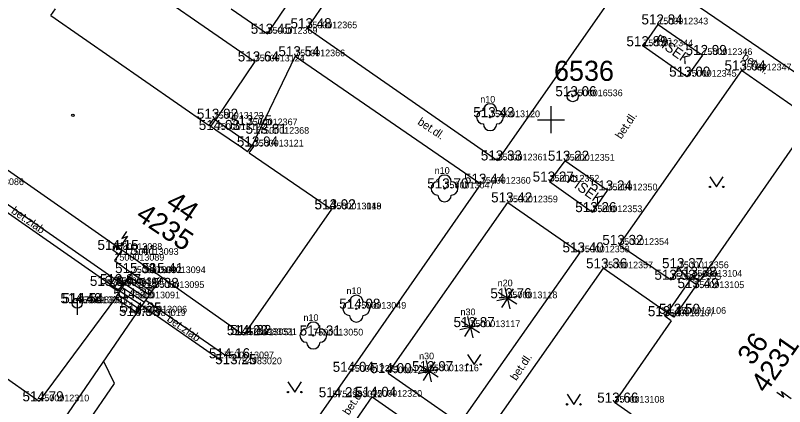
# Model space of a CAD drawing. Extents: x -669251 to -668549, y -1128351 to -1127698.
# Drawn here: x -668989.9 to -668932.6, y -1127921.4 to -1127892.2 of the extents above; entities that cross this region are included whole.
import ezdxf

# ---------------------------------------------------------------- set-up
doc = ezdxf.new("R2010")
doc.units = 0
for name, color, linetype in [('Vrstva 1', 7, 'Continuous'), ('Vrstva 10', 7, 'Continuous'), ('Vrstva 11', 7, 'Continuous'), ('Vrstva 2', 7, 'Continuous'), ('Vrstva 21', 7, 'Continuous'), ('Vrstva 22', 7, 'Continuous'), ('Vrstva 24', 7, 'Continuous'), ('Vrstva 27', 7, 'Continuous'), ('Vrstva 3', 7, 'Continuous'), ('Vrstva 36', 7, 'Continuous'), ('Vrstva 40', 7, 'Continuous'), ('Vrstva 42', 7, 'Continuous'), ('Vrstva 43', 7, 'Continuous'), ('Vrstva 44', 7, 'Continuous'), ('Vrstva 47', 7, 'Continuous'), ('Vrstva 5', 7, 'Continuous'), ('Vrstva 58', 7, 'Continuous'), ('Vrstva 6', 7, 'Continuous'), ('Vrstva 61', 7, 'Continuous'), ('Vrstva 63', 7, 'Continuous')]:
    doc.layers.add(name, color=color, linetype=linetype)

msp = doc.modelspace()

# ---------------------------------------------------------------- linework, layer by layer
at = {"layer": 'Vrstva 1'}
for p, q in [((-668968.152, -1127893.186), (-668968.152, -1127893.186)), ((-668942.004, -1127892.9), (-668942.004, -1127892.9)), ((-668971.113, -1127893.598), (-668971.113, -1127893.598)), ((-668943.121, -1127894.526), (-668943.121, -1127894.526)), ((-668969.052, -1127895.274), (-668969.052, -1127895.274)), ((-668938.713, -1127895.179), (-668938.713, -1127895.179)), ((-668972.065, -1127895.659), (-668972.065, -1127895.659)), ((-668935.793, -1127896.328), (-668935.793, -1127896.328)), ((-668939.885, -1127896.794), (-668939.885, -1127896.794)), ((-668948.374, -1127898.252), (-668948.374, -1127898.252)), ((-668975.121, -1127899.931), (-668975.121, -1127899.931)), ((-668954.534, -1127899.815), (-668954.534, -1127899.815)), ((-668972.591, -1127900.414), (-668972.591, -1127900.414)), ((-668974.965, -1127900.77), (-668974.965, -1127900.77)), ((-668971.732, -1127901.049), (-668971.732, -1127901.049)), ((-668972.14, -1127902), (-668972.14, -1127902)), ((-668953.974, -1127903.041), (-668953.974, -1127903.041)), ((-668948.971, -1127903.063), (-668948.971, -1127903.063)), ((-668950.109, -1127904.616), (-668950.109, -1127904.616)), ((-668957.927, -1127905.125), (-668957.927, -1127905.125)), ((-668955.225, -1127904.774), (-668955.225, -1127904.774)), ((-668945.78, -1127905.276), (-668945.78, -1127905.276)), ((-668953.204, -1127906.167), (-668953.204, -1127906.167)), ((-668966.349, -1127906.681), (-668966.349, -1127906.681)), ((-668966.345, -1127906.688), (-668966.345, -1127906.688)), ((-668946.914, -1127906.894), (-668946.914, -1127906.894)), ((-668982.675, -1127909.708), (-668982.675, -1127909.708)), ((-668944.918, -1127909.338), (-668944.918, -1127909.338)), ((-668981.455, -1127910.08), (-668981.455, -1127910.08)), ((-668947.848, -1127909.893), (-668947.848, -1127909.893)), ((-668982.522, -1127910.509), (-668982.522, -1127910.509)), ((-668981.221, -1127911.439), (-668981.221, -1127911.439)), ((-668979.441, -1127911.438), (-668979.441, -1127911.438)), ((-668946.11, -1127911.079), (-668946.11, -1127911.079)), ((-668940.472, -1127911.072), (-668940.472, -1127911.072)), ((-668941.039, -1127911.936), (-668941.039, -1127911.936)), ((-668939.463, -1127911.706), (-668939.463, -1127911.706)), ((-668983.093, -1127912.392), (-668983.093, -1127912.392)), ((-668982.348, -1127912.262), (-668982.348, -1127912.262)), ((-668979.542, -1127912.543), (-668979.542, -1127912.543)), ((-668939.317, -1127912.557), (-668939.317, -1127912.557)), ((-668985.29, -1127913.682), (-668985.29, -1127913.682)), ((-668985.152, -1127913.68), (-668985.152, -1127913.68)), ((-668981.354, -1127913.322), (-668981.354, -1127913.322)), ((-668953.239, -1127913.311), (-668953.239, -1127913.311)), ((-668980.823, -1127914.376), (-668980.823, -1127914.376)), ((-668964.498, -1127914.091), (-668964.498, -1127914.091)), ((-668980.928, -1127914.633), (-668980.928, -1127914.633)), ((-668941.525, -1127914.651), (-668941.525, -1127914.651)), ((-668940.671, -1127914.472), (-668940.671, -1127914.472)), ((-668956.005, -1127915.465), (-668956.005, -1127915.465)), ((-668972.898, -1127916.064), (-668972.898, -1127916.064)), ((-668972.649, -1127916.053), (-668972.649, -1127916.053)), ((-668967.704, -1127916.089), (-668967.704, -1127916.089)), ((-668974.35, -1127917.788), (-668974.35, -1127917.788)), ((-668973.762, -1127918.23), (-668973.762, -1127918.23)), ((-668964.983, -1127918.797), (-668964.983, -1127918.797)), ((-668962.136, -1127918.896), (-668962.136, -1127918.896)), ((-668959.092, -1127918.751), (-668959.092, -1127918.751)), ((-668966.283, -1127920.691), (-668966.283, -1127920.691)), ((-668963.314, -1127920.66), (-668963.314, -1127920.66)), ((-668988.115, -1127920.994), (-668988.115, -1127920.994)), ((-668945.266, -1127921.095), (-668945.266, -1127921.095))]:
    msp.add_line(p, q, dxfattribs=at)
at = {"layer": 'Vrstva 10'}
for p, q in [((-668932.638, -1127872.499), (-668953.974, -1127903.041)), ((-668958.428, -1127878.805), (-668968.152, -1127893.186)), ((-668984.978, -1127886.729), (-668972.065, -1127895.659)), ((-668971.113, -1127893.598), (-668968.407, -1127889.606)), ((-668941.646, -1127889.728), (-668930.773, -1127897.183)), ((-668973.834, -1127891.738), (-668971.113, -1127893.598)), ((-668968.152, -1127893.186), (-668953.974, -1127903.041)), ((-668943.121, -1127894.526), (-668942.004, -1127892.9)), ((-668942.004, -1127892.9), (-668938.713, -1127895.179)), ((-668939.885, -1127896.794), (-668943.121, -1127894.526)), ((-668969.052, -1127895.274), (-668972.264, -1127901.915)), ((-668969.052, -1127895.274), (-668955.225, -1127904.774)), ((-668938.713, -1127895.179), (-668939.885, -1127896.794)), ((-668972.065, -1127895.659), (-668974.998, -1127900.017)), ((-668935.793, -1127896.328), (-668944.918, -1127909.338)), ((-668931.053, -1127899.649), (-668935.793, -1127896.328)), ((-668948.971, -1127903.063), (-668950.109, -1127904.616)), ((-668945.78, -1127905.276), (-668948.971, -1127903.063)), ((-668992.837, -1127904.672), (-668981.814, -1127912.341)), ((-668950.109, -1127904.616), (-668946.914, -1127906.894)), ((-668993.125, -1127905.08), (-668982.1, -1127912.776)), ((-668955.225, -1127904.774), (-668964.983, -1127918.797)), ((-668946.914, -1127906.894), (-668945.78, -1127905.276)), ((-668962.136, -1127918.896), (-668953.204, -1127906.167)), ((-668953.204, -1127906.167), (-668947.848, -1127909.893)), ((-668944.918, -1127909.338), (-668941.039, -1127911.936)), ((-668947.848, -1127909.893), (-668956.786, -1127922.617)), ((-668946.11, -1127911.079), (-668955.055, -1127923.813)), ((-668941.343, -1127914.388), (-668946.11, -1127911.079)), ((-668941.039, -1127911.936), (-668940.472, -1127911.072)), ((-668940.472, -1127911.072), (-668939.646, -1127911.969)), ((-669000.837, -1127912.018), (-668988.115, -1127920.994)), ((-668982.449, -1127913.307), (-668988.115, -1127920.994)), ((-668980.174, -1127913.447), (-668974.208, -1127917.583)), ((-668986.272, -1127922.324), (-668980.823, -1127914.376)), ((-668980.459, -1127913.855), (-668974.492, -1127917.993)), ((-668962.136, -1127918.896), (-668956.786, -1127922.617)), ((-668971.938, -1127933.04), (-668963.314, -1127920.66)), ((-668963.314, -1127920.66), (-668958.065, -1127924.311))]:
    msp.add_line(p, q, dxfattribs=at)
msp.add_lwpolyline([(-668964.983, -1127918.797), (-668983.234, -1127944.915)], dxfattribs=at)
at = {"layer": 'Vrstva 11'}
for p, q in [((-668981.972, -1127909.72), (-668982.522, -1127910.509)), ((-668982.522, -1127910.509), (-668981.221, -1127911.439)), ((-668981.397, -1127911.706), (-668981.221, -1127911.439)), ((-668981.221, -1127911.439), (-668979.542, -1127912.543)), ((-668981.748, -1127912.241), (-668981.573, -1127911.974)), ((-668981.573, -1127911.974), (-668981.397, -1127911.706)), ((-668981.573, -1127911.974), (-668979.909, -1127913.068)), ((-668981.397, -1127911.706), (-668979.725, -1127912.805)), ((-668978.987, -1127911.759), (-668979.542, -1127912.543)), ((-668982.1, -1127912.776), (-668981.924, -1127912.509)), ((-668981.924, -1127912.509), (-668981.814, -1127912.341)), ((-668981.924, -1127912.509), (-668980.276, -1127913.593)), ((-668981.814, -1127912.341), (-668981.748, -1127912.241)), ((-668981.748, -1127912.241), (-668980.092, -1127913.33)), ((-668979.725, -1127912.805), (-668979.542, -1127912.543)), ((-668982.449, -1127913.307), (-668982.276, -1127913.043)), ((-668982.276, -1127913.043), (-668982.1, -1127912.776)), ((-668982.276, -1127913.043), (-668980.642, -1127914.117)), ((-668982.1, -1127912.776), (-668980.459, -1127913.855)), ((-668980.092, -1127913.33), (-668979.909, -1127913.068)), ((-668979.909, -1127913.068), (-668979.725, -1127912.805)), ((-668982.449, -1127913.307), (-668980.823, -1127914.376)), ((-668980.459, -1127913.855), (-668980.276, -1127913.593)), ((-668980.276, -1127913.593), (-668980.174, -1127913.447)), ((-668980.174, -1127913.447), (-668980.092, -1127913.33)), ((-668980.823, -1127914.376), (-668980.642, -1127914.117)), ((-668980.642, -1127914.117), (-668980.459, -1127913.855))]:
    msp.add_line(p, q, dxfattribs=at)
at = {"layer": 'Vrstva 21'}
for p, q in [((-668982.505, -1127919.664), (-668983.319, -1127918.017)), ((-668984.984, -1127923.265), (-668982.505, -1127919.664))]:
    msp.add_line(p, q, dxfattribs=at)
at = {"layer": 'Vrstva 22'}
for p, q in [((-668953.247, -1127913.271), (-668953.419, -1127912.517)), ((-668952.805, -1127912.621), (-668953.219, -1127913.277)), ((-668953.273, -1127913.291), (-668953.929, -1127912.877)), ((-668953.199, -1127913.303), (-668952.445, -1127913.131)), ((-668954.033, -1127913.491), (-668953.279, -1127913.319)), ((-668953.259, -1127913.345), (-668953.673, -1127914.001)), ((-668953.231, -1127913.351), (-668953.059, -1127914.105)), ((-668952.549, -1127913.745), (-668953.205, -1127913.331)), ((-668956.013, -1127915.425), (-668956.185, -1127914.671)), ((-668955.571, -1127914.775), (-668955.985, -1127915.431)), ((-668956.799, -1127915.645), (-668956.045, -1127915.473)), ((-668956.039, -1127915.445), (-668956.695, -1127915.031)), ((-668956.025, -1127915.499), (-668956.439, -1127916.155)), ((-668955.997, -1127915.505), (-668955.825, -1127916.259)), ((-668955.315, -1127915.899), (-668955.971, -1127915.485)), ((-668955.965, -1127915.457), (-668955.211, -1127915.285)), ((-668959.126, -1127918.731), (-668959.782, -1127918.317)), ((-668959.1, -1127918.711), (-668959.272, -1127917.957)), ((-668958.658, -1127918.061), (-668959.072, -1127918.717)), ((-668959.886, -1127918.931), (-668959.132, -1127918.759)), ((-668959.112, -1127918.785), (-668959.526, -1127919.441)), ((-668959.084, -1127918.791), (-668958.912, -1127919.545)), ((-668958.402, -1127919.185), (-668959.058, -1127918.771)), ((-668959.052, -1127918.743), (-668958.298, -1127918.571))]:
    msp.add_line(p, q, dxfattribs=at)
for centre, radius in [((-668954.534, -1127899.815), 0.05), ((-668957.927, -1127905.125), 0.05), ((-668953.239, -1127913.311), 0.04), ((-668964.498, -1127914.091), 0.05), ((-668956.005, -1127915.465), 0.04), ((-668967.704, -1127916.089), 0.05), ((-668959.092, -1127918.751), 0.04)]:
    msp.add_circle(centre, radius, dxfattribs=at)
for centre, start, end in [((-668954.534, -1127899.315), 0, 180), ((-668955.034, -1127899.815), 90, 270), ((-668954.034, -1127899.815), 270, 90), ((-668954.534, -1127900.315), 180, 0), ((-668958.427, -1127905.125), 90, 270), ((-668957.927, -1127904.625), 0, 180), ((-668957.427, -1127905.125), 270, 90), ((-668957.927, -1127905.625), 180, 0), ((-668964.498, -1127913.591), 0, 180), ((-668964.998, -1127914.091), 90, 270), ((-668963.998, -1127914.091), 270, 90), ((-668964.498, -1127914.591), 180, 0), ((-668967.704, -1127915.589), 0, 180), ((-668968.204, -1127916.089), 90, 270), ((-668967.204, -1127916.089), 270, 90), ((-668967.704, -1127916.589), 180, 0)]:
    msp.add_arc(centre, 0.5, start, end, dxfattribs=at)
at = {"layer": 'Vrstva 24'}
for p, q in [((-668981.557, -1127908.688), (-668982.047, -1127909.413)), ((-668981.624, -1127908.34), (-668981.974, -1127908.859)), ((-668981.974, -1127908.859), (-668981.557, -1127908.688)), ((-668982.001, -1127909.148), (-668982.047, -1127909.413)), ((-668982.45, -1127909.386), (-668982.675, -1127909.708)), ((-668982.196, -1127910.042), (-668982.675, -1127909.708)), ((-668982.047, -1127909.413), (-668981.819, -1127909.271)), ((-668933.162, -1127920.312), (-668932.657, -1127920.682)), ((-668932.657, -1127920.682), (-668932.812, -1127920.259)), ((-668932.812, -1127920.259), (-668932.106, -1127920.776))]:
    msp.add_line(p, q, dxfattribs=at)
at = {"layer": 'Vrstva 27'}
for p, q in [((-668982.554, -1127912.575), (-668982.142, -1127911.949)), ((-668985.29, -1127913.307), (-668985.29, -1127914.557))]:
    msp.add_line(p, q, dxfattribs=at)
msp.add_lwpolyline([(-668982.242, -1127912.781), (-668981.829, -1127912.154), (-668982.456, -1127911.742), (-668982.868, -1127912.369)], close=True, dxfattribs=at)
msp.add_circle((-668985.29, -1127913.682), 0.375, dxfattribs=at)
at = {"layer": 'Vrstva 36'}
for p, q in [((-668938.156, -1127904.268), (-668937.656, -1127905.018)), ((-668937.656, -1127905.018), (-668937.156, -1127904.268)), ((-668956.228, -1127917.496), (-668955.728, -1127918.246)), ((-668955.728, -1127918.246), (-668955.228, -1127917.496)), ((-668969.59, -1127919.555), (-668969.09, -1127920.305)), ((-668969.09, -1127920.305), (-668968.59, -1127919.555)), ((-668948.796, -1127920.47), (-668948.296, -1127921.22)), ((-668948.296, -1127921.22), (-668947.796, -1127920.47))]:
    msp.add_line(p, q, dxfattribs=at)
for centre in [(-668938.156, -1127905.018), (-668937.156, -1127905.018), (-668956.228, -1127918.245), (-668955.228, -1127918.245), (-668969.589, -1127920.304), (-668968.589, -1127920.304), (-668948.796, -1127921.22), (-668947.796, -1127921.22)]:
    msp.add_circle(centre, 0.05, dxfattribs=at)
at = {"layer": 'Vrstva 5'}
for p, q in [((-668987.253, -1127892.235), (-668986.912, -1127891.744)), ((-668987.253, -1127892.235), (-668975.463, -1127900.424)), ((-668975.463, -1127900.424), (-668975.121, -1127899.931)), ((-668975.34, -1127900.509), (-668974.998, -1127900.017)), ((-668975.121, -1127899.931), (-668974.998, -1127900.017)), ((-668974.998, -1127900.017), (-668972.264, -1127901.915)), ((-668974.965, -1127900.77), (-668975.34, -1127900.509)), ((-668930.734, -1127900.212), (-668938.966, -1127912.052)), ((-668981.972, -1127909.72), (-668993.739, -1127901.513)), ((-668972.594, -1127902.397), (-668972.973, -1127902.136)), ((-668972.594, -1127902.397), (-668972.264, -1127901.915)), ((-668972.47, -1127902.481), (-668972.14, -1127902)), ((-668972.264, -1127901.915), (-668972.14, -1127902)), ((-668972.47, -1127902.481), (-668966.349, -1127906.681)), ((-668966.349, -1127906.681), (-668972.898, -1127916.064)), ((-668981.455, -1127910.08), (-668981.972, -1127909.72)), ((-668978.987, -1127911.759), (-668979.441, -1127911.438)), ((-668972.898, -1127916.064), (-668978.987, -1127911.759)), ((-668939.646, -1127911.969), (-668941.343, -1127914.388)), ((-668939.646, -1127911.969), (-668939.463, -1127911.706)), ((-668939.148, -1127912.314), (-668939.646, -1127911.969)), ((-668938.966, -1127912.052), (-668939.463, -1127911.706)), ((-668939.148, -1127912.314), (-668939.317, -1127912.557)), ((-668941.525, -1127914.651), (-668941.343, -1127914.388)), ((-668940.85, -1127914.73), (-668941.343, -1127914.388)), ((-668941.032, -1127914.993), (-668945.266, -1127921.095)), ((-668941.032, -1127914.993), (-668941.525, -1127914.651)), ((-668940.671, -1127914.472), (-668940.85, -1127914.73)), ((-668944.034, -1127921.95), (-668945.266, -1127921.095))]:
    msp.add_line(p, q, dxfattribs=at)
at = {"layer": 'Vrstva 58'}
msp.add_circle((-668985.618, -1127899.681), 0.0875, dxfattribs=at)
at = {"layer": 'Vrstva 6'}
for p, q in [((-668972.973, -1127902.136), (-668974.965, -1127900.77)), ((-668981.455, -1127910.08), (-668979.441, -1127911.438)), ((-668939.317, -1127912.557), (-668940.671, -1127914.472))]:
    msp.add_line(p, q, dxfattribs=at)
at = {"layer": 'Vrstva 61'}
for p, q in [((-668950, -1127899), (-668950, -1127901)), ((-668951, -1127900), (-668949, -1127900))]:
    msp.add_line(p, q, dxfattribs=at)
at = {"layer": 'Vrstva 63'}
for radius in [0.412, 0.412, 0.05, 0.05]:
    msp.add_circle((-668948.374, -1127898.252), radius, dxfattribs=at)

# ---------------------------------------------------------------- texts
at = {"layer": 'Vrstva 2'}
for s, p in [('7500012343', (-668942.004, -1127892.9)), ('7500012369', (-668971.113, -1127893.598)), ('7500012365', (-668968.152, -1127893.186)), ('7500012344', (-668943.121, -1127894.526)), ('7500012366', (-668969.052, -1127895.274)), ('7500012346', (-668938.713, -1127895.179)), ('7500013124', (-668972.065, -1127895.659)), ('7500012347', (-668935.793, -1127896.328)), ('7500012345', (-668939.885, -1127896.794)), ('7500016536', (-668948.374, -1127898.252)), ('7500013123', (-668975.121, -1127899.931)), ('7500013120', (-668954.534, -1127899.815)), ('7500012367', (-668972.591, -1127900.414)), ('7500013122', (-668974.965, -1127900.77)), ('7500012368', (-668971.732, -1127901.049)), ('7500013121', (-668972.14, -1127902)), ('7500012361', (-668953.974, -1127903.041)), ('7500012351', (-668948.971, -1127903.063)), ('7500012352', (-668950.109, -1127904.616)), ('7500013086', (-668992.981, -1127904.876)), ('7500013047', (-668957.927, -1127905.125)), ('7500012360', (-668955.225, -1127904.774)), ('7500012350', (-668945.78, -1127905.276)), ('7500012359', (-668953.204, -1127906.167)), ('7500013048', (-668966.349, -1127906.681)), ('7500013119', (-668966.345, -1127906.688)), ('7500012353', (-668946.914, -1127906.894)), ('7500013088', (-668982.675, -1127909.708)), ('7500012354', (-668944.918, -1127909.338)), ('7500013093', (-668981.455, -1127910.08)), ('7500012358', (-668947.848, -1127909.893)), ('7500013089', (-668982.522, -1127910.509)), ('7500013092', (-668981.221, -1127911.439)), ('7500013094', (-668979.441, -1127911.438)), ('7500012357', (-668946.11, -1127911.079)), ('7500012356', (-668940.472, -1127911.072)), ('7500012355', (-668941.039, -1127911.936)), ('7500013104', (-668939.463, -1127911.706)), ('5754983018', (-668983.093, -1127912.392)), ('7500013090', (-668982.348, -1127912.262)), ('7500013095', (-668979.542, -1127912.543)), ('7500013105', (-668939.317, -1127912.557)), ('7500013087', (-668985.29, -1127913.682)), ('5754983017', (-668985.152, -1127913.68)), ('7500013091', (-668981.354, -1127913.322)), ('7500013118', (-668953.239, -1127913.311)), ('7500013049', (-668964.498, -1127914.091)), ('5754983019', (-668980.928, -1127914.633)), ('7500013096', (-668980.823, -1127914.376)), ('7500013107', (-668941.525, -1127914.651)), ('7500013106', (-668940.671, -1127914.472)), ('7500013117', (-668956.005, -1127915.465)), ('7500013051', (-668972.898, -1127916.064)), ('5754983021', (-668972.649, -1127916.053)), ('7500013050', (-668967.704, -1127916.089)), ('7500013097', (-668974.35, -1127917.788)), ('5754983020', (-668973.762, -1127918.23)), ('7500012321', (-668964.983, -1127918.797)), ('7500012319', (-668962.136, -1127918.896)), ('7500013116', (-668959.092, -1127918.751)), ('7500012320', (-668963.314, -1127920.66)), ('7500012310', (-668988.115, -1127920.994)), ('5754983022', (-668966.283, -1127920.691)), ('7500013108', (-668945.266, -1127921.095))]:
    msp.add_text(s, height=0.5, dxfattribs=at).set_placement(p)
at = {"layer": 'Vrstva 3'}
for s, p in [('513.48 ', (-668969.404, -1127893.186)), ('512.84 ', (-668943.256, -1127892.9)), ('513.45 ', (-668972.365, -1127893.598)), ('512.89 ', (-668944.376, -1127894.526)), ('513.64 ', (-668973.331, -1127895.659)), ('513.54 ', (-668970.304, -1127895.274)), ('512.99 ', (-668939.97, -1127895.179)), ('513.00 ', (-668941.194, -1127896.794)), ('513.04 ', (-668937.067, -1127896.328)), ('513.06 ', (-668949.67, -1127898.252)), ('513.92 ', (-668976.375, -1127899.931)), ('513.43 ', (-668955.786, -1127899.815)), ('514.03 ', (-668976.239, -1127900.77)), ('513.75 ', (-668973.843, -1127900.414)), ('513.81 ', (-668972.747, -1127901.049)), ('513.94 ', (-668973.394, -1127902)), ('513.33 ', (-668955.226, -1127903.041)), ('513.22 ', (-668950.223, -1127903.063)), ('513.44 ', (-668956.477, -1127904.774)), ('513.27 ', (-668951.361, -1127904.616)), ('513.70 ', (-668959.215, -1127905.125)), ('513.24 ', (-668947.032, -1127905.276)), ('513.42 ', (-668954.456, -1127906.167)), ('514.02 ', (-668967.619, -1127906.688)), ('513.92 ', (-668967.603, -1127906.681)), ('513.26 ', (-668948.188, -1127906.894)), ('513.32 ', (-668946.17, -1127909.338)), ('514.15 ', (-668983.785, -1127909.708)), ('513.40 ', (-668949.136, -1127909.893)), ('515.41 ', (-668982.47, -1127910.08)), ('513.36 ', (-668947.384, -1127911.079)), ('513.37 ', (-668941.724, -1127911.072)), ('515.38 ', (-668982.473, -1127911.439)), ('515.41 ', (-668980.456, -1127911.438)), ('513.38 ', (-668940.715, -1127911.706)), ('513.87 ', (-668983.6, -1127912.262)), ('513.33 ', (-668942.291, -1127911.936)), ('513.94 ', (-668984.347, -1127912.392)), ('515.38 ', (-668980.794, -1127912.543)), ('513.49 ', (-668940.572, -1127912.557)), ('514.25 ', (-668982.606, -1127913.322)), ('513.76 ', (-668954.513, -1127913.311)), ('514.48 ', (-668986.542, -1127913.682)), ('514.54 ', (-668986.404, -1127913.68)), ('514.25 ', (-668982.075, -1127914.376)), ('514.08 ', (-668965.772, -1127914.091)), ('513.50 ', (-668941.959, -1127914.472)), ('514.35 ', (-668982.18, -1127914.633)), ('513.44 ', (-668942.777, -1127914.651)), ('513.87 ', (-668957.257, -1127915.465)), ('514.23 ', (-668974.15, -1127916.064)), ('514.32 ', (-668973.901, -1127916.053)), ('514.31 ', (-668968.719, -1127916.089)), ('514.16 ', (-668975.483, -1127917.788)), ('513.25 ', (-668975.014, -1127918.23)), ('514.04 ', (-668966.257, -1127918.797)), ('514.00 ', (-668963.445, -1127918.896)), ('513.97 ', (-668960.346, -1127918.751)), ('514.21 ', (-668967.298, -1127920.691)), ('514.04 ', (-668964.588, -1127920.66)), ('514.79 ', (-668989.37, -1127920.994)), ('513.66 ', (-668946.554, -1127921.095))]:
    msp.add_text(s, height=0.75, dxfattribs=at).set_placement(p)
at = {"layer": 'Vrstva 40'}
for s, rotation, p in [('bet.dl.', 326.31918, (-668935.814, -1127895.446)), ('bet.dl.', 326.31918, (-668959.989, -1127900.3)), ('bet.dl.', 56.31918, (-668944.762, -1127901.494)), ('bet.zlab', 325.08461, (-668990.253, -1127906.928)), ('bet.zlab', 325.08461, (-668978.663, -1127914.979)), ('bet.dl.', 56.31918, (-668952.585, -1127919.496)), ('bet.dl.', 56.31918, (-668965.063, -1127922.078))]:
    msp.add_text(s, height=0.6, rotation=rotation, dxfattribs=at).set_placement(p)
at = {"layer": 'Vrstva 42'}
for rotation, p in [(324.97472, (-668942.37, -1127894.198)), (324.51155, (-668948.868, -1127904.641))]:
    msp.add_text('PÍSEK', height=0.75, rotation=rotation, dxfattribs=at).set_placement(p)
at = {"layer": 'Vrstva 43'}
for s, rotation, p in [('4235', 326.009, (-668981.014, -1127907.362)), ('4231', 55.19076, (-668933.988, -1127920.459))]:
    msp.add_text(s, height=1.5, rotation=rotation, dxfattribs=at).set_placement(p)
at = {"layer": 'Vrstva 44'}
for s, rotation, p in [('44', 326.009, (-668978.78, -1127906.456)), ('36', 55.19076, (-668934.986, -1127918.392))]:
    msp.add_text(s, height=1.5, rotation=rotation, dxfattribs=at).set_placement(p)
at = {"layer": 'Vrstva 47'}
for s, height, p in [('n10', 0.499, (-668955.264, -1127898.729)), ('n10', 0.499, (-668958.657, -1127904.039)), ('n20', 0.5, (-668953.969, -1127912.425)), ('n10', 0.499, (-668965.228, -1127913.005)), ('n30', 0.5, (-668956.735, -1127914.579)), ('n10', 0.499, (-668968.434, -1127915.003)), ('n30', 0.5, (-668959.822, -1127917.865))]:
    msp.add_text(s, height=height, dxfattribs=at).set_placement(p)
at = {"layer": 'Vrstva 63'}
msp.add_text('6536', height=1.5, dxfattribs=at).set_placement((-668949.768, -1127897.108))
msp.add_text('6536', height=1.5, dxfattribs=at).set_placement((-668949.768, -1127897.108))

doc.saveas('drawing.dxf')
